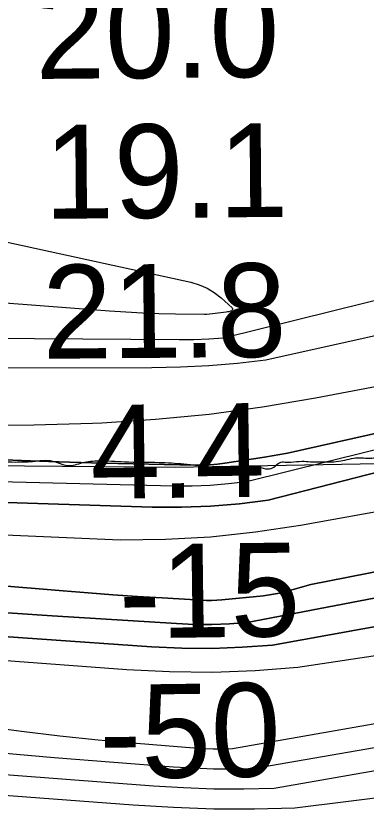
# Model space of a CAD drawing. Extents: x 3445503 to 3483459, y 540493 to 566012.
# Drawn here: x 3463483 to 3463733, y 552191 to 552758 of the extents above; entities that cross this region are included whole.
import ezdxf

# ---------------------------------------------------------------- set-up
doc = ezdxf.new("R2010")
doc.units = 0
for name, color, linetype in [('V-RIVR-EDGE', 7, 'Continuous'), ('V-RIVR-RANG', 7, 'Continuous'), ('V-RRAP-RVMT', 7, 'Continuous'), ('V-TOPO-DPTH', 7, 'Continuous'), ('V-TOPO-MAJR', 7, 'Continuous'), ('V-TOPO-MINR', 7, 'Continuous'), ('V-TOPO-WATR', 7, 'Continuous')]:
    doc.layers.add(name, color=color, linetype=linetype)

msp = doc.modelspace()

# ---------------------------------------------------------------- linework, layer by layer
at = {"layer": 'V-RIVR-EDGE'}
for points in [[(3463494.85, 552439.11), (3463509.11, 552439.42), (3463519.88, 552436.27), (3463530.66, 552438.33), (3463542.13, 552439.69), (3463560.56, 552438.95), (3463585.24, 552438.54), (3463602.96, 552437.45), (3463621.73, 552435.32), (3463646.06, 552434.91), (3463650.24, 552435.6), (3463656.14, 552435.24), (3463663.09, 552433.83), (3463667.27, 552435.21), (3463672.14, 552438.67), (3463676.32, 552438.66), (3463679.44, 552438.65), (3463687.44, 552439.33), (3463693.35, 552438.97), (3463699.96, 552438.95), (3463713.51, 552439.27), (3463725.69, 552441.67), (3463737.16, 552441.64), (3463742.37, 552441.63), (3463748.28, 552438.83), (3463754.88, 552437.42), (3463767.04, 552436), (3463792.07, 552435.25), (3463816.06, 552435.54), (3463829.96, 552435.5), (3463835.87, 552433.75), (3463840.73, 552431.3), (3463843.86, 552431.64), (3463851.86, 552435.45), (3463858.47, 552437.52), (3463862.99, 552437.16), (3463867.85, 552435.75), (3463871.33, 552434.01), (3463875.5, 552434), (3463881.75, 552433.98), (3463892.89, 552438.82), (3463898.8, 552438.81), (3463910.27, 552437.74), (3463930.44, 552441.16), (3463957.56, 552443.88), (3463962.08, 552443.52), (3463964.51, 552439.69), (3463967.29, 552440.38), (3463969.03, 552443.15), (3463972.17, 552444.54), (3463980.16, 552445.91), (3463985.03, 552445.89), (3463991.29, 552445.53), (3463995.11, 552444.48), (3463999.28, 552444.82), (3464004.5, 552447.24), (3464011.45, 552447.22), (3464015.97, 552447.56), (3464034.4, 552449.6), (3464046.23, 552453.04), (3464057.01, 552454.41), (3464062.23, 552454.05), (3464070.57, 552452.98), (3464076.82, 552453.66), (3464082.05, 552457.13), (3464085.52, 552456.77), (3464090.39, 552456.41), (3464092.46, 552450.5), (3464093.85, 552449.1), (3464095.93, 552449.1), (3464096.63, 552450.83), (3464097.34, 552453.96), (3464101.16, 552454.65), (3464103.59, 552454.29), (3464103.58, 552450.12), (3464105.67, 552449.42), (3464117.14, 552451.13), (3464127.58, 552455.28), (3464138.38, 552461.51), (3464157.16, 552468.06), (3464159.25, 552469.45), (3464159.61, 552472.93), (3464163.09, 552475.7), (3464167.26, 552475.69), (3464170.4, 552477.77), (3464173.19, 552482.97), (3464177.71, 552482.96), (3464181.88, 552483.65), (3464187.46, 552491.28), (3464191.64, 552492.66), (3464213.91, 552502.69), (3464241.76, 552519.3), (3464260.58, 552535.94), (3464282.15, 552544.93), (3464300.96, 552559.48), (3464326.38, 552576.8), (3464355.64, 552598.98), (3464394.64, 552624.61), (3464417.96, 552636.72), (3464439.54, 552647.44), (3464444.41, 552648.82), (3464446.5, 552650.55), (3464453.1, 552650.19), (3464457.27, 552650.52), (3464463.88, 552650.86), (3464472.93, 552654.31), (3464481.97, 552658.46), (3464499.37, 552665.72), (3464540.77, 552675.35), (3464563.03, 552681.2), (3464578.69, 552687.77), (3464587.04, 552690.18), (3464602.34, 552692.23), (3464627.73, 552698.77), (3464651.04, 552704.97), (3464658, 552707.73), (3464675.4, 552714.3), (3464689.67, 552720.87), (3464699.05, 552722.23), (3464715.06, 552727.06), (3464730.37, 552734.32), (3464744.63, 552738.46), (3464763.42, 552743.63), (3464800.28, 552749.45), (3464814.9, 552754.28), (3464839.95, 552763.95), (3464844.47, 552763.94), (3464849.34, 552764.62), (3464857.68, 552764.6), (3464870.9, 552768.39), (3464882.03, 552770.45), (3464891.42, 552770.77), (3464900.45, 552770.75), (3464903.93, 552771.44), (3464907.06, 552773.17), (3464910.54, 552773.86), (3464922.02, 552775.22), (3464941.84, 552777.95), (3464960.27, 552781.73), (3464966.54, 552784.15), (3464977.66, 552785.51), (3464995.05, 552786.16), (3465006.88, 552789.61), (3465024.96, 552791.3), (3465034.02, 552791.76)], [(3463269.95, 552445.92), (3463288.38, 552446.23), (3463298.81, 552445.85), (3463309.58, 552443.74), (3463319.31, 552443.72), (3463329.74, 552443.69), (3463341.56, 552443.31), (3463349.55, 552439.82), (3463353.72, 552439.81), (3463358.93, 552440.84), (3463368.68, 552443.94), (3463377.02, 552443.92), (3463380.84, 552442.87), (3463389.18, 552442.85), (3463395.44, 552442.83), (3463406.21, 552441.07), (3463417.33, 552440), (3463437.84, 552440.29), (3463447.93, 552440.62), (3463461.48, 552439.89), (3463482.69, 552438.79), (3463494.85, 552439.11)]]:
    msp.add_spline(points, degree=3, dxfattribs=at)
at = {"layer": 'V-RRAP-RVMT'}
msp.add_lwpolyline([(3464153.41, 552461.74), (3464143.75, 552459.88), (3464004.9, 552450.49), (3464005.16, 552447.08), (3463858.77, 552435.92), (3463742.39, 552430.51), (3463742.09, 552437.6), (3463596.75, 552434.86), (3463461.89, 552436.12), (3463461.88, 552439.47), (3463348.35, 552441.58), (3463348.24, 552443.66), (3463328.32, 552444.55), (3463328.43, 552445.57), (3463173.04, 552454.31), (3463173.02, 552452.69)], dxfattribs=at)
at = {"layer": 'V-TOPO-DPTH'}
for points in [[(3464730.25, 552749.59), (3463661.47, 552511.56), (3463641.19, 552509.26), (3463620.88, 552507.49), (3463600.51, 552506.52), (3463580.1, 552506.09), (3463049.14, 552505.21)], [(3462368.5, 552494.88), (3462582.11, 552468.49), (3462689.09, 552456.75), (3462842.61, 552440.82), (3462880.21, 552437.05), (3462917.82, 552433.45), (3462955.46, 552430.12), (3462993.11, 552426.96), (3463030.8, 552424.22), (3463580.41, 552406.52), (3463601.2, 552406.49), (3463621.95, 552407.19), (3463642.63, 552409), (3463663.27, 552411.53), (3464693.81, 552676.25)], [(3462368.5, 552494.88), (3462582.11, 552468.49), (3462689.09, 552456.75), (3462842.61, 552440.82), (3462880.21, 552437.05), (3462917.82, 552433.45), (3462955.46, 552430.12), (3462993.11, 552426.96), (3463030.8, 552424.22), (3463580.41, 552406.52), (3463601.2, 552406.49), (3463621.95, 552407.19), (3463642.63, 552409), (3463663.27, 552411.53), (3464693.81, 552676.25)], [(3463938.02, 552503.64), (3463677.08, 552445.22), (3463671.64, 552444.08), (3463666.16, 552443.09), (3463660.67, 552442.2), (3463632.27, 552437.94), (3463626.99, 552437.28), (3463621.7, 552436.81), (3463616.39, 552436.61), (3463611.07, 552436.59), (3463544.69, 552438.05), (3463506.18, 552439.13), (3463467.68, 552440.5), (3463429.2, 552442.33), (3462955.48, 552471.17), (3462935.48, 552472.5), (3462915.48, 552473.95), (3462895.5, 552475.59), (3462875.52, 552477.35), (3462785.85, 552485.71), (3462734.06, 552491.01), (3462043.1, 552583.25)], [(3462043.1, 552583.25), (3462734.06, 552491.01), (3462785.85, 552485.71), (3462875.52, 552477.35), (3462895.5, 552475.59), (3462915.48, 552473.95), (3462935.48, 552472.5), (3462955.48, 552471.17), (3463429.2, 552442.33), (3463467.68, 552440.5), (3463506.18, 552439.13), (3463544.69, 552438.05), (3463611.07, 552436.59), (3463616.39, 552436.61), (3463621.7, 552436.81), (3463626.99, 552437.28), (3463632.27, 552437.94), (3463660.67, 552442.2), (3463666.16, 552443.09), (3463671.64, 552444.08), (3463677.08, 552445.22), (3463938.02, 552503.64)], [(3464690.94, 552547.3), (3463693.64, 552351.18), (3463689.45, 552350), (3463685.26, 552348.82), (3463681.07, 552347.64), (3463676.87, 552346.47), (3463672.66, 552345.4), (3463668.42, 552344.49), (3463664.13, 552343.8), (3463659.82, 552343.25), (3463630.2, 552340.31), (3463626.49, 552340.03), (3463622.78, 552339.86), (3463619.06, 552339.88), (3463615.33, 552340), (3463587.45, 552341.63), (3463569.79, 552342.73), (3463552.13, 552343.91), (3463534.49, 552345.22), (3463516.85, 552346.63), (3462979.4, 552391.39)], [(3462979.4, 552391.39), (3463516.85, 552346.63), (3463534.49, 552345.22), (3463552.13, 552343.91), (3463569.79, 552342.73), (3463587.45, 552341.63), (3463615.33, 552340), (3463619.06, 552339.88), (3463622.78, 552339.86), (3463626.49, 552340.03), (3463630.2, 552340.31), (3463659.82, 552343.25), (3463664.13, 552343.8), (3463668.42, 552344.49), (3463672.66, 552345.4), (3463676.87, 552346.47), (3463681.07, 552347.64), (3463685.26, 552348.82), (3463689.45, 552350), (3463693.64, 552351.18), (3464690.94, 552547.3)], [(3464403.72, 552468.97), (3463648.24, 552324.16), (3463635.6, 552323.21), (3463622.96, 552322.68), (3463610.3, 552322.77), (3463597.64, 552323.27), (3463508.89, 552328.94), (3463451.85, 552332.69), (3463394.82, 552336.57), (3463337.81, 552340.64), (3463280.8, 552344.85), (3462979.2, 552367.61), (3462950.24, 552369.69), (3462921.26, 552371.62), (3462892.27, 552373.34), (3462863.27, 552374.92), (3462759.36, 552380.19), (3462678.42, 552384.71), (3462597.53, 552389.79), (3462516.69, 552395.71)], [(3462516.69, 552395.71), (3462597.53, 552389.79), (3462678.42, 552384.71), (3462759.36, 552380.19), (3462863.27, 552374.92), (3462892.27, 552373.34), (3462921.26, 552371.62), (3462950.24, 552369.69), (3462979.2, 552367.61), (3463280.8, 552344.85), (3463337.81, 552340.64), (3463394.82, 552336.57), (3463451.85, 552332.69), (3463508.89, 552328.94), (3463597.64, 552323.27), (3463610.3, 552322.77), (3463622.96, 552322.68), (3463635.6, 552323.21), (3463648.24, 552324.16), (3464403.72, 552468.97)], [(3464316.96, 552425.48), (3463666.28, 552308), (3463644.72, 552306.41), (3463623.14, 552305.54), (3463601.56, 552305.76), (3463579.96, 552306.71), (3463416.23, 552318.06), (3463333.92, 552323.77), (3463251.62, 552329.48), (3463169.32, 552335.2), (3463087.01, 552340.92), (3462960.76, 552349.7), (3462941.58, 552350.91), (3462922.39, 552351.94), (3462903.18, 552352.72), (3462883.97, 552353.32), (3462488.91, 552363.1)], [(3462488.91, 552363.1), (3462883.97, 552353.32), (3462903.18, 552352.72), (3462922.39, 552351.94), (3462941.58, 552350.91), (3462960.76, 552349.7), (3463087.01, 552340.92), (3463169.32, 552335.2), (3463251.62, 552329.48), (3463333.92, 552323.77), (3463416.23, 552318.06), (3463579.96, 552306.71), (3463601.56, 552305.76), (3463623.14, 552305.54), (3463644.72, 552306.41), (3463666.28, 552308), (3464316.96, 552425.48)]]:
    msp.add_lwpolyline(points, dxfattribs=at)
at = {"layer": 'V-TOPO-MAJR'}
msp.add_lwpolyline([(3464647.86, 552436.93), (3463684.31, 552291.84), (3463653.83, 552289.61), (3463623.33, 552288.44), (3463592.82, 552288.85), (3463562.29, 552290.32), (3463217.5, 552315.93), (3463168.49, 552319.52), (3463119.47, 552323.02), (3463070.44, 552326.42), (3463021.41, 552329.74), (3462945.59, 552334.78), (3462934.46, 552335.42), (3462923.32, 552335.91), (3462912.17, 552336.19), (3462901.02, 552336.33), (3462161.83, 552338.57)], dxfattribs=at)
at = {"layer": 'V-TOPO-MINR'}
for points in [[(3464714.02, 552795.77), (3463631.24, 552527.39), (3463620.71, 552526.55), (3463610.15, 552526.13), (3463599.57, 552526), (3463392.63, 552527.51), (3463312.14, 552529.08), (3463231.71, 552531.96), (3463151.38, 552536.8), (3463071.11, 552542.96), (3462966.8, 552552.24), (3462938.75, 552554.91), (3462910.72, 552557.81), (3462882.74, 552561.06), (3462854.77, 552564.54), (3462776.09, 552574.84), (3462708.82, 552583.7), (3462641.55, 552592.65), (3462574.3, 552601.72), (3462507.06, 552610.87)], [(3464730.25, 552749.59), (3463661.47, 552511.56), (3463641.19, 552509.26), (3463620.88, 552507.49), (3463600.51, 552506.52), (3463580.1, 552506.09), (3463049.14, 552505.21)], [(3464714.9, 552689.36), (3463647.77, 552424.73), (3463634.81, 552423.14), (3463621.82, 552421.99), (3463608.79, 552421.52), (3463595.74, 552421.51), (3463432.42, 552425.62), (3463346.35, 552428.37), (3463260.31, 552431.89), (3463174.34, 552436.57), (3463088.4, 552442.02), (3462976.1, 552449.91), (3462946.35, 552452.13), (3462916.61, 552454.5), (3462886.89, 552457.13), (3462857.19, 552459.91), (3462735.14, 552471.85), (3462656.93, 552480.1), (3462578.8, 552489.13), (3462298.84, 552528.75)], [(3464693.81, 552676.25), (3463663.27, 552411.53), (3463642.63, 552409), (3463621.95, 552407.19), (3463601.2, 552406.49), (3463580.41, 552406.52), (3463030.8, 552424.22), (3462993.11, 552426.96), (3462955.46, 552430.12), (3462917.82, 552433.45), (3462880.21, 552437.05), (3462842.61, 552440.82), (3462689.09, 552456.75), (3462582.11, 552468.49), (3462368.5, 552494.88)], [(3462954.03, 552659.25), (3463149.87, 552644.43), (3463229.11, 552636.76), (3463308.02, 552626.92), (3463386.46, 552613.79), (3463464.58, 552598.48), (3463608.03, 552567.25), (3463613.94, 552565.46), (3463619.56, 552563.09)], [(3463871.8, 552517.51), (3463697.12, 552484.31), (3463659.14, 552477.95), (3463621.04, 552472.7), (3463582.74, 552469.11), (3463544.32, 552466.64), (3463537.62, 552466.36), (3463495.76, 552465.18), (3463453.9, 552464.82), (3463412.04, 552465.67), (3463370.19, 552467.32), (3462936.15, 552490.75), (3462925.28, 552491.4), (3462914.42, 552492.13), (3462903.57, 552492.97), (3462892.72, 552493.89), (3462840.71, 552498.6), (3462813.26, 552501.37), (3462785.86, 552504.5), (3462758.52, 552508.19), (3462731.24, 552512.24), (3462703.99, 552516.6), (3462062.99, 552602.14)], [(3463619.56, 552563.09), (3463624.73, 552559.86), (3463629.6, 552556.05), (3463637.43, 552548.85), (3463637.73, 552548.27), (3463637.8, 552547.73), (3463637.54, 552547.25), (3463637.05, 552546.81), (3463635.21, 552546.21), (3463634.27, 552546), (3463633.31, 552545.85), (3463623.32, 552544.58), (3463619.15, 552544.27), (3463617.76, 552544.26), (3463596.92, 552544.51), (3463585.12, 552544.77), (3463573.31, 552545.17), (3463561.52, 552545.81), (3463549.74, 552546.6), (3462926.14, 552594.42)], [(3464690.94, 552547.3), (3463693.64, 552351.18), (3463689.45, 552350), (3463685.26, 552348.82), (3463681.07, 552347.64), (3463676.87, 552346.47), (3463672.66, 552345.4), (3463668.42, 552344.49), (3463664.13, 552343.8), (3463659.82, 552343.25), (3463630.2, 552340.31), (3463626.49, 552340.03), (3463622.78, 552339.86), (3463619.06, 552339.88), (3463615.33, 552340), (3463587.45, 552341.63), (3463569.79, 552342.73), (3463552.13, 552343.91), (3463534.49, 552345.22), (3463516.85, 552346.63), (3462979.4, 552391.39)], [(3464403.72, 552468.97), (3463648.24, 552324.16), (3463635.6, 552323.21), (3463622.96, 552322.68), (3463610.3, 552322.77), (3463597.64, 552323.27), (3463508.89, 552328.94), (3463451.85, 552332.69), (3463394.82, 552336.57), (3463337.81, 552340.64), (3463280.8, 552344.85), (3462979.2, 552367.61), (3462950.24, 552369.69), (3462921.26, 552371.62), (3462892.27, 552373.34), (3462863.27, 552374.92), (3462759.36, 552380.19), (3462678.42, 552384.71), (3462597.53, 552389.79), (3462516.69, 552395.71)], [(3463821.41, 552417.72), (3463686.27, 552393.51), (3463654.22, 552388.71), (3463622.06, 552385.15), (3463589.76, 552383.43), (3463557.36, 552382.95), (3462927.68, 552410.4), (3462923.36, 552410.76), (3462919.03, 552411.12), (3462914.71, 552411.46), (3462910.38, 552411.8), (3462906.05, 552412.14), (3462901.72, 552412.48), (3462897.4, 552412.82), (3462893.07, 552413.16), (3462882.65, 552413.99), (3462873.12, 552414.8), (3462863.59, 552415.65), (3462854.07, 552416.59), (3462844.55, 552417.58), (3462543.56, 552450.32)], [(3464316.96, 552425.48), (3463666.28, 552308), (3463644.72, 552306.41), (3463623.14, 552305.54), (3463601.56, 552305.76), (3463579.96, 552306.71), (3463416.23, 552318.06), (3463333.92, 552323.77), (3463251.62, 552329.48), (3463169.32, 552335.2), (3463087.01, 552340.92), (3462960.76, 552349.7), (3462941.58, 552350.91), (3462922.39, 552351.94), (3462903.18, 552352.72), (3462883.97, 552353.32), (3462488.91, 552363.1)], [(3464671.64, 552415.16), (3463637.73, 552233.76), (3463630.84, 552233.62), (3463623.95, 552233.64), (3463617.06, 552233.9), (3463610.18, 552234.32), (3463569.08, 552237.54), (3463541.68, 552239.97), (3463514.33, 552242.78), (3463487.03, 552246.14), (3463459.78, 552249.87), (3463316.54, 552270.98), (3463263.48, 552278.79), (3463210.42, 552286.57), (3463157.36, 552294.32), (3463104.29, 552302.05)], [(3464688.62, 552398.86), (3463652.58, 552219.62), (3463638.34, 552219.33), (3463624.12, 552219.37), (3463609.9, 552219.9), (3463595.69, 552220.76), (3463510.37, 552227.41), (3463453.56, 552232.29), (3463396.81, 552237.79), (3463340.15, 552244.19), (3463283.56, 552251.2), (3462984.36, 552290.69), (3462954.9, 552294.23), (3462925.39, 552297.3), (3462895.82, 552299.67), (3462866.21, 552301.57), (3462836.56, 552302.79), (3462806.91, 552303.55), (3462777.24, 552303.64), (3462747.57, 552303.27), (3462055.48, 552286.82)], [(3464701.32, 552386.24), (3463667.43, 552205.48), (3463645.85, 552205.04), (3463624.28, 552205.08), (3463602.73, 552205.87), (3463581.19, 552207.15), (3463450.15, 552217.2), (3463363.13, 552224.27), (3463276.15, 552231.87), (3463189.25, 552240.25), (3463102.4, 552249.16), (3462980.81, 552262.2), (3462954.01, 552264.78), (3462927.18, 552266.98), (3462900.31, 552268.6), (3462873.41, 552269.83), (3462724.64, 552275.04), (3462623.32, 552277.73), (3462522.01, 552279.26)], [(3464481.67, 552290.64), (3463682.28, 552191.34), (3463653.36, 552190.74), (3463624.45, 552190.78), (3463595.56, 552191.81), (3463566.69, 552193.5), (3463265.11, 552216.24), (3463208.98, 552220.6), (3463152.87, 552225.14), (3463096.78, 552229.92), (3463040.7, 552234.88), (3462959.37, 552242.26), (3462943.96, 552243.5), (3462928.53, 552244.53), (3462913.09, 552245.26), (3462897.63, 552245.79), (3462377.02, 552258.18)]]:
    msp.add_lwpolyline(points, dxfattribs=at)
at = {"layer": 'V-TOPO-WATR'}
msp.add_lwpolyline([(3463938.02, 552503.64), (3463677.08, 552445.22), (3463671.64, 552444.08), (3463666.16, 552443.09), (3463660.67, 552442.2), (3463632.27, 552437.94), (3463626.99, 552437.28), (3463621.7, 552436.81), (3463616.39, 552436.61), (3463611.07, 552436.59), (3463544.69, 552438.05), (3463506.18, 552439.13), (3463467.68, 552440.5), (3463429.2, 552442.33), (3462955.48, 552471.17), (3462935.48, 552472.5), (3462915.48, 552473.95), (3462895.5, 552475.59), (3462875.52, 552477.35), (3462785.85, 552485.71), (3462734.06, 552491.01), (3462043.1, 552583.25)], dxfattribs=at)

# ---------------------------------------------------------------- texts
at = {"layer": 'V-RIVR-RANG'}
for s, rotation, p in [('20.0', 0.4783, (3463497.03, 552712.49)), ('19.1', 0.4783, (3463503.39, 552612.54)), ('21.8', 0.4783, (3463502.11, 552512.53)), ('4.4', 0.7649, (3463536.6, 552412.39)), ('-15', 0.7649, (3463556.94, 552312.65)), ('-50', 0.7649, (3463543, 552212.45))]:
    msp.add_text(s, height=67, rotation=rotation, dxfattribs=at).set_placement(p)

doc.saveas('drawing.dxf')
